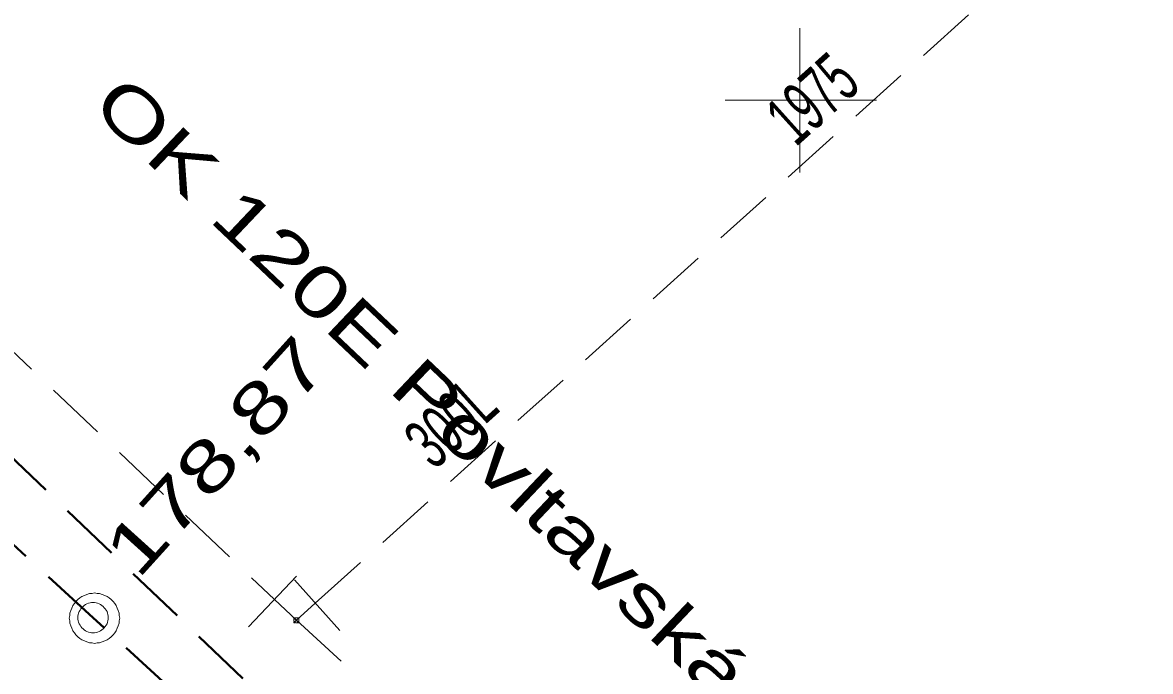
# Model space of a CAD drawing. Extents: x -740851 to -738888, y -1041382 to -1040235.
# Drawn here: x -739715.38 to -739693.06, y -1040561.3 to -1040548.46 of the extents above; entities that cross this region are included whole.
import ezdxf

# ---------------------------------------------------------------- set-up
doc = ezdxf.new("R2010")
doc.units = 0
doc.header["$LTSCALE"] = 0.4
doc.linetypes.add('MEDIUM_DASHED', pattern=[4.5, 3, -1.5])
for name, color, linetype, lineweight in [('1', 7, 'Continuous', 13), ('18', 7, 'Continuous', 13), ('8', 7, 'Continuous', 13)]:
    doc.layers.add(name, color=color, linetype=linetype, lineweight=lineweight)

msp = doc.modelspace()

# ---------------------------------------------------------------- linework, layer by layer
at = {"layer": '1'}
for p, q in [((-739700, -1040548.571), (-739700, -1040551.429)), ((-739701.48, -1040550), (-739698.48, -1040550))]:
    msp.add_line(p, q, dxfattribs=at)
at = {"layer": '18', "linetype": 'MEDIUM_DASHED', "lineweight": 40}
msp.add_line((-739703.155, -1040570.156), (-739713.989, -1040560.24), dxfattribs=at)
msp.add_lwpolyline([(-739713.989, -1040560.24), (-739725.522, -1040549.684), (-739737.438, -1040539.524), (-739739.89, -1040537.56)], dxfattribs=at)
at = {"layer": '18'}
for points in [[(-739713.459, -1040560.25), (-739713.469, -1040560.2), (-739713.469, -1040560.15), (-739713.489, -1040560.1), (-739713.509, -1040560.05), (-739713.529, -1040560), (-739713.559, -1040559.96), (-739713.589, -1040559.92), (-739713.629, -1040559.88), (-739713.669, -1040559.85), (-739713.709, -1040559.82), (-739713.759, -1040559.8), (-739713.809, -1040559.78), (-739713.859, -1040559.76), (-739713.909, -1040559.76), (-739713.959, -1040559.75), (-739714.009, -1040559.76), (-739714.059, -1040559.76), (-739714.109, -1040559.78), (-739714.159, -1040559.8), (-739714.209, -1040559.82), (-739714.249, -1040559.85), (-739714.289, -1040559.88), (-739714.329, -1040559.92), (-739714.359, -1040559.96), (-739714.389, -1040560), (-739714.409, -1040560.05), (-739714.429, -1040560.1), (-739714.449, -1040560.15), (-739714.449, -1040560.2), (-739714.459, -1040560.25), (-739714.449, -1040560.3), (-739714.449, -1040560.35), (-739714.429, -1040560.4), (-739714.409, -1040560.45), (-739714.389, -1040560.5), (-739714.359, -1040560.54), (-739714.329, -1040560.58), (-739714.289, -1040560.62), (-739714.249, -1040560.65), (-739714.209, -1040560.68), (-739714.159, -1040560.7), (-739714.109, -1040560.72), (-739714.059, -1040560.74), (-739714.009, -1040560.74), (-739713.959, -1040560.75), (-739713.909, -1040560.74), (-739713.859, -1040560.74), (-739713.809, -1040560.72), (-739713.759, -1040560.7), (-739713.709, -1040560.68), (-739713.669, -1040560.65), (-739713.629, -1040560.62), (-739713.589, -1040560.58), (-739713.559, -1040560.54), (-739713.529, -1040560.5), (-739713.509, -1040560.45), (-739713.489, -1040560.4), (-739713.469, -1040560.35), (-739713.469, -1040560.3)], [(-739713.689, -1040560.24), (-739713.689, -1040560.21), (-739713.695, -1040560.18), (-739713.701, -1040560.15), (-739713.713, -1040560.12), (-739713.731, -1040560.09), (-739713.749, -1040560.066), (-739713.767, -1040560.042), (-739713.791, -1040560.018), (-739713.815, -1040560), (-739713.839, -1040559.982), (-739713.869, -1040559.964), (-739713.899, -1040559.952), (-739713.929, -1040559.946), (-739713.959, -1040559.94), (-739713.989, -1040559.94), (-739714.019, -1040559.94), (-739714.049, -1040559.946), (-739714.079, -1040559.952), (-739714.109, -1040559.964), (-739714.139, -1040559.982), (-739714.163, -1040560), (-739714.187, -1040560.018), (-739714.211, -1040560.042), (-739714.229, -1040560.066), (-739714.247, -1040560.09), (-739714.265, -1040560.12), (-739714.277, -1040560.15), (-739714.283, -1040560.18), (-739714.289, -1040560.21), (-739714.289, -1040560.24), (-739714.289, -1040560.27), (-739714.283, -1040560.3), (-739714.277, -1040560.33), (-739714.265, -1040560.36), (-739714.247, -1040560.39), (-739714.229, -1040560.414), (-739714.211, -1040560.438), (-739714.187, -1040560.462), (-739714.163, -1040560.48), (-739714.139, -1040560.498), (-739714.109, -1040560.516), (-739714.079, -1040560.528), (-739714.049, -1040560.534), (-739714.019, -1040560.54), (-739713.989, -1040560.54), (-739713.959, -1040560.54), (-739713.929, -1040560.534), (-739713.899, -1040560.528), (-739713.869, -1040560.516), (-739713.839, -1040560.498), (-739713.815, -1040560.48), (-739713.791, -1040560.462), (-739713.767, -1040560.438), (-739713.749, -1040560.414), (-739713.731, -1040560.39), (-739713.713, -1040560.36), (-739713.701, -1040560.33), (-739713.695, -1040560.3), (-739713.689, -1040560.27)]]:
    msp.add_lwpolyline(points, close=True, dxfattribs=at)
at = {"layer": '8'}
for p, q in [((-739710.912, -1040560.42), (-739709.964, -1040559.42)), ((-739709.104, -1040560.494), (-739710.005, -1040559.494)), ((-739710.014, -1040560.341), (-739709.914, -1040560.241)), ((-739710.014, -1040560.241), (-739709.914, -1040560.341)), ((-739710.014, -1040560.241), (-739710.014, -1040560.261)), ((-739710.014, -1040560.241), (-739709.994, -1040560.241)), ((-739710.014, -1040560.341), (-739710.014, -1040560.321)), ((-739710.014, -1040560.341), (-739709.994, -1040560.341)), ((-739709.914, -1040560.241), (-739709.934, -1040560.241)), ((-739709.914, -1040560.341), (-739709.934, -1040560.341)), ((-739709.914, -1040560.241), (-739709.914, -1040560.261)), ((-739709.914, -1040560.341), (-739709.914, -1040560.321))]:
    msp.add_line(p, q, dxfattribs=at)
at = {"layer": '8', "linetype": 'MEDIUM_DASHED', "lineweight": 25}
for p, q in [((-739710.4, -1040559.88), (-739709.965, -1040560.292)), ((-739709.965, -1040560.292), (-739702.46, -1040567.11))]:
    msp.add_line(p, q, dxfattribs=at)
at = {"layer": '8', "linetype": 'MEDIUM_DASHED', "lineweight": 40}
msp.add_lwpolyline([(-739800.406, -1040510.509), (-739783.874, -1040510.33), (-739769.682, -1040516.575), (-739747.937, -1040528.604), (-739744.345, -1040531.012), (-739722.292, -1040550.654), (-739710.435, -1040562.012), (-739703.68, -1040568.1)], dxfattribs=at)
at = {"layer": '8', "linetype": 'MEDIUM_DASHED', "lineweight": 25}
for points in [[(-739743.43, -1040529.83), (-739735.19, -1040536.61), (-739721.3, -1040549.54), (-739710.4, -1040559.88)], [(-739709.965, -1040560.292), (-739709.59, -1040559.954), (-739693.06, -1040545.06)]]:
    msp.add_lwpolyline(points, dxfattribs=at)
at = {"layer": '8'}
msp.add_lwpolyline([(-739709.914, -1040560.291), (-739709.914, -1040560.286), (-739709.915, -1040560.281), (-739709.916, -1040560.276), (-739709.918, -1040560.271), (-739709.921, -1040560.266), (-739709.924, -1040560.262), (-739709.927, -1040560.258), (-739709.931, -1040560.254), (-739709.935, -1040560.251), (-739709.939, -1040560.248), (-739709.944, -1040560.245), (-739709.949, -1040560.243), (-739709.954, -1040560.242), (-739709.959, -1040560.241), (-739709.964, -1040560.241), (-739709.969, -1040560.241), (-739709.974, -1040560.242), (-739709.979, -1040560.243), (-739709.984, -1040560.245), (-739709.989, -1040560.248), (-739709.993, -1040560.251), (-739709.997, -1040560.254), (-739710.001, -1040560.258), (-739710.004, -1040560.262), (-739710.007, -1040560.266), (-739710.01, -1040560.271), (-739710.012, -1040560.276), (-739710.013, -1040560.281), (-739710.014, -1040560.286), (-739710.014, -1040560.291), (-739710.014, -1040560.296), (-739710.013, -1040560.301), (-739710.012, -1040560.306), (-739710.01, -1040560.311), (-739710.007, -1040560.316), (-739710.004, -1040560.32), (-739710.001, -1040560.324), (-739709.997, -1040560.328), (-739709.993, -1040560.331), (-739709.989, -1040560.334), (-739709.984, -1040560.337), (-739709.979, -1040560.339), (-739709.974, -1040560.34), (-739709.969, -1040560.341), (-739709.964, -1040560.341), (-739709.959, -1040560.341), (-739709.954, -1040560.34), (-739709.949, -1040560.339), (-739709.944, -1040560.337), (-739709.939, -1040560.334), (-739709.935, -1040560.331), (-739709.931, -1040560.328), (-739709.927, -1040560.324), (-739709.924, -1040560.32), (-739709.921, -1040560.316), (-739709.918, -1040560.311), (-739709.916, -1040560.306), (-739709.915, -1040560.301), (-739709.914, -1040560.296)], close=True, dxfattribs=at)

# ---------------------------------------------------------------- texts
at = {"layer": '18', "width": 1.4}
for s, rotation, p in [('OK 120E Povltavská - 72P', 316.536, (-739714.059, -1040550.151)), ('178,87', 47.881, (-739713.103, -1040559.501))]:
    msp.add_text(s, height=1, rotation=rotation, dxfattribs=at).set_placement(p)
at = {"layer": '8', "width": 0.6}
for s, p in [('1975', (-739700.081, -1040550.935)), ('300L', (-739707.237, -1040557.334))]:
    msp.add_text(s, height=1, rotation=42.02, dxfattribs=at).set_placement(p)

doc.saveas('drawing.dxf')
